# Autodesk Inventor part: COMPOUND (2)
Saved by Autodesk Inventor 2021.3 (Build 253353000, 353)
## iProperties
Created: 2022-06
Part Number: COMPOUND (2)
Material: Generic
Document SubType Name: Modeling
Designer: Administrator
Density: 1 g/cm^3
Appearance: Default
Title: COMPOUND (2)
Author: Administrator
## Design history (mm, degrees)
feature "Body1"
feature "Body2"
feature "Body3"
feature "Body4"
feature "Body5"
feature "Body6"
feature "Body7"
body "Solid1"
body "Solid2"
body "Solid3"
body "Solid4"
body "Solid5"
body "Solid6"
body "Solid7"
